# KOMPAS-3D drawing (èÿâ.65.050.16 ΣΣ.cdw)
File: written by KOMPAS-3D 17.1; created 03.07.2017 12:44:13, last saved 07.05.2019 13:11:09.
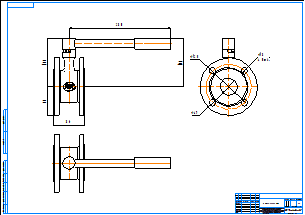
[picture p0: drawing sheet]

Sheet 1: A1, landscape

Title block, sheet 1: name: КШГ.65.050.16 фф; material: Внимание! Данный продукт является объектом авторского права ООО «Торговый Дом АДЛ». / Запрещается изменение, копирование, распространение / (в том числе путем копирования на другие сайты и ресурсы в Интернете) / или любое иное использование информации и объектов без предварительного / согласия правообладателя (ООО «Торговый Дом АДЛ»).; sheets: 1; organisation: ООО "Торговый дом АДЛ"; sheet format: A1; stored path: C:\Users\kka\KOMPAS_Work\!Trash\СС02 СС03 ФФ Смотровые стекла\СС01.cdw

Views: Спереди 1, Проекционный вид 2, Проекционный вид 3
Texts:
  Klimkovich
  ADL
Dimensions and other numbers on the sheet: 280; 134; 86; 133; 80; 125; 49; 18; 4 Отв.; 1:1; 1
